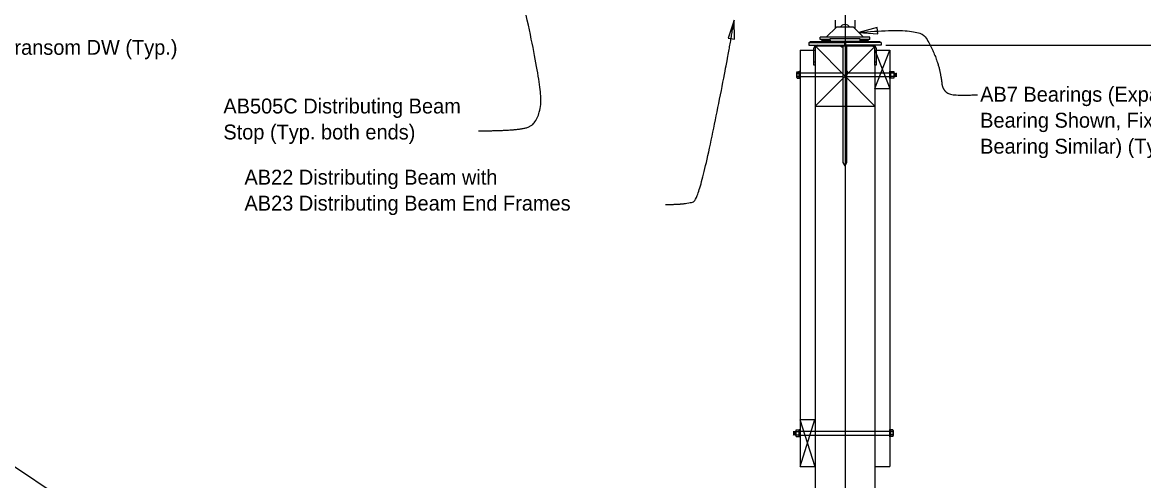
# Model space of a CAD drawing. Extents: x 3 to 58.1, y 3.3 to 34.2.
# Drawn here: x 28.56 to 47.33, y 13.88 to 21.56 of the extents above; entities that cross this region are included whole.
import ezdxf

# ---------------------------------------------------------------- set-up
doc = ezdxf.new("R2010")
doc.units = 0
for name, color, linetype in [('CL_Minor', 7, 'Continuous'), ('Dimension', 7, 'Continuous'), ('Miscellaneous', 7, 'Continuous'), ('SteelMisc', 7, 'Continuous'), ('SteelMisc_h', 7, 'Continuous'), ('TextStructures', 7, 'Continuous'), ('Wood', 7, 'Continuous')]:
    doc.layers.add(name, color=color, linetype=linetype)

msp = doc.modelspace()

# ---------------------------------------------------------------- linework, layer by layer
at = {"layer": 'CL_Minor'}
msp.add_line((42.335, 22.925), (42.335, 7.572), dxfattribs=at)
at = {"layer": 'Dimension'}
msp.add_line((43.017, 21.175), (55.391, 21.175), dxfattribs=at)
for points in [[(40.478, 21.592), (40.378, 21.292), (40.483, 21.275)], [(42.569, 21.389), (42.885, 21.365), (42.875, 21.47)]]:
    msp.add_lwpolyline(points, close=True, dxfattribs=at)
for points in [[(36.198, 19.74), (36.833, 19.74), (37.195, 19.851), (37.283, 20.5), (36.796, 22.544)], [(27.05, 21.127), (26.868, 21.142), (26.902, 21.296), (27.192, 21.546), (28.589, 21.877), (29.418, 22.176)], [(39.329, 18.506), (39.72, 18.506), (39.897, 18.616), (40.384, 20.985), (40.478, 21.592)], [(42.569, 21.389), (43.587, 21.481), (43.791, 21.128), (43.902, 20.843), (43.949, 20.607), (43.968, 20.434), (44.122, 20.318), (44.551, 20.345)]]:
    msp.add_open_spline(points, degree=2, dxfattribs=at)
at = {"layer": 'Miscellaneous'}
for p, q in [((42.855, 21.092), (42.854, 21.092)), ((19.956, 19.761), (32.606, 11.328))]:
    msp.add_line(p, q, dxfattribs=at)
at = {"layer": 'SteelMisc'}
for p, q in [((42.168, 21.592), (42.168, 21.455)), ((42.501, 21.592), (42.501, 21.454)), ((42.192, 21.477), (42.019, 21.311)), ((42.478, 21.477), (42.192, 21.477)), ((42.478, 21.477), (42.645, 21.311)), ((41.731, 21.217), (41.731, 21.175)), ((41.731, 21.217), (42.324, 21.217)), ((42.751, 21.311), (41.918, 21.311)), ((41.918, 21.269), (41.918, 21.311)), ((42.085, 21.269), (41.918, 21.269)), ((42.085, 21.259), (42.085, 21.248)), ((42.324, 21.217), (42.324, 21.175)), ((42.939, 21.217), (42.345, 21.217)), ((42.345, 21.217), (42.345, 21.175)), ((42.751, 21.269), (42.585, 21.269)), ((42.585, 21.259), (42.585, 21.248)), ((42.751, 21.269), (42.751, 21.311)), ((42.939, 21.217), (42.939, 21.175)), ((41.731, 21.175), (42.324, 21.175)), ((41.814, 20.842), (41.814, 21.123)), ((41.835, 21.123), (41.835, 20.842)), ((41.866, 21.175), (42.803, 21.175)), ((42.803, 21.155), (41.866, 21.155)), ((42.939, 21.175), (42.345, 21.175)), ((42.835, 20.842), (42.835, 21.123)), ((42.855, 21.123), (42.855, 20.842)), ((41.814, 20.898), (41.835, 20.898)), ((41.835, 20.842), (41.814, 20.842)), ((42.835, 20.898), (42.855, 20.898)), ((42.855, 20.842), (42.835, 20.842)), ((41.528, 20.634), (41.528, 20.717)), ((41.532, 20.73), (41.57, 20.73)), ((41.532, 20.703), (41.57, 20.703)), ((42.366, 20.742), (42.366, 20.741)), ((43.153, 20.73), (43.099, 20.73)), ((43.153, 20.703), (43.099, 20.703)), ((43.157, 20.634), (43.157, 20.717)), ((43.159, 20.696), (43.157, 20.699)), ((43.158, 20.644), (43.157, 20.657)), ((43.162, 20.655), (43.158, 20.644)), ((43.163, 20.707), (43.159, 20.696)), ((43.168, 20.644), (43.162, 20.655)), ((43.168, 20.644), (43.163, 20.707)), ((43.169, 20.696), (43.163, 20.707)), ((43.173, 20.655), (43.168, 20.644)), ((43.173, 20.707), (43.169, 20.696)), ((43.179, 20.644), (43.173, 20.707)), ((43.179, 20.696), (43.173, 20.707)), ((43.179, 20.644), (43.173, 20.655)), ((43.184, 20.707), (43.179, 20.696)), ((43.183, 20.655), (43.179, 20.644)), ((43.189, 20.644), (43.183, 20.655)), ((43.189, 20.644), (43.184, 20.707)), ((43.19, 20.696), (43.184, 20.707)), ((43.193, 20.655), (43.189, 20.644)), ((43.194, 20.707), (43.19, 20.696)), ((43.197, 20.648), (43.193, 20.655)), ((43.197, 20.668), (43.194, 20.707)), ((43.197, 20.701), (43.194, 20.707)), ((43.197, 20.648), (43.197, 20.701)), ((41.532, 20.648), (41.57, 20.648)), ((41.532, 20.621), (41.57, 20.621)), ((43.153, 20.648), (43.099, 20.648)), ((43.153, 20.621), (43.099, 20.621)), ((43.158, 20.644), (43.157, 20.646)), ((41.472, 14.703), (41.472, 14.65)), ((41.472, 14.703), (41.476, 14.696)), ((41.472, 14.683), (41.475, 14.644)), ((41.472, 14.65), (41.475, 14.644)), ((41.475, 14.644), (41.48, 14.655)), ((41.476, 14.696), (41.48, 14.707)), ((41.48, 14.707), (41.486, 14.644)), ((41.48, 14.707), (41.486, 14.696)), ((41.48, 14.655), (41.486, 14.644)), ((41.486, 14.696), (41.491, 14.707)), ((41.486, 14.644), (41.49, 14.655)), ((41.49, 14.655), (41.496, 14.644)), ((41.491, 14.707), (41.496, 14.644)), ((41.491, 14.707), (41.497, 14.696)), ((41.496, 14.644), (41.5, 14.655)), ((41.497, 14.696), (41.501, 14.707)), ((41.5, 14.655), (41.507, 14.644)), ((41.501, 14.707), (41.507, 14.644)), ((41.501, 14.707), (41.507, 14.696)), ((41.507, 14.696), (41.512, 14.707)), ((41.507, 14.644), (41.511, 14.655)), ((41.511, 14.655), (41.513, 14.652)), ((41.512, 14.707), (41.513, 14.694)), ((41.512, 14.707), (41.513, 14.705)), ((41.513, 14.717), (41.513, 14.634)), ((41.517, 14.73), (41.57, 14.73)), ((41.517, 14.703), (41.57, 14.703)), ((41.517, 14.648), (41.57, 14.648)), ((43.137, 14.73), (43.099, 14.73)), ((43.137, 14.703), (43.099, 14.703)), ((43.137, 14.648), (43.099, 14.648)), ((43.141, 14.717), (43.141, 14.634)), ((41.517, 14.621), (41.57, 14.621)), ((43.137, 14.621), (43.099, 14.621))]:
    msp.add_line(p, q, dxfattribs=at)
for points in [[(41.751, 21.22), (41.751, 21.238), (42.918, 21.238), (42.918, 21.217)], [(42.085, 21.248), (41.939, 21.248), (41.939, 21.238)], [(42.085, 21.259), (42.001, 21.259), (42.001, 21.269)], [(42.668, 21.269), (42.668, 21.259), (42.585, 21.259)], [(42.731, 21.238), (42.731, 21.248), (42.585, 21.248)]]:
    msp.add_lwpolyline(points, dxfattribs=at)
for points in [[(42.585, 21.238), (42.085, 21.238), (42.085, 21.288), (42.585, 21.288)], [(42.241, 21.175), (42.428, 21.175), (42.428, 21.155), (42.241, 21.155)], [(41.57, 20.737), (41.585, 20.737), (41.585, 20.614), (41.57, 20.614)], [(43.085, 20.737), (43.099, 20.737), (43.099, 20.614), (43.085, 20.614)], [(41.585, 14.614), (41.57, 14.614), (41.57, 14.737), (41.585, 14.737)], [(43.099, 14.614), (43.085, 14.614), (43.085, 14.737), (43.099, 14.737)]]:
    msp.add_lwpolyline(points, close=True, dxfattribs=at)
for centre, radius, start, end in [((42.335, 21.415), 0.104, 36.8424, 143.1576), ((41.866, 21.123), 0.052, 90, 180), ((41.866, 21.123), 0.0312, 90, 180), ((42.803, 21.123), 0.052, 0, 90), ((42.803, 21.123), 0.0312, 0, 90), ((41.553, 20.717), 0.0248, 146.5255, 213.4745), ((41.621, 20.675), 0.093, 162.8979, 197.1021), ((43.132, 20.717), 0.0248, 326.5255, 33.4745), ((43.064, 20.675), 0.093, 342.8979, 17.1021), ((41.553, 20.634), 0.0248, 146.5255, 213.4745), ((43.132, 20.634), 0.0248, 326.5255, 33.4745), ((41.537, 14.717), 0.0248, 146.5255, 213.4745), ((41.606, 14.675), 0.093, 162.8979, 197.1021), ((41.537, 14.634), 0.0248, 146.5255, 213.4745), ((43.116, 14.717), 0.0248, 326.5255, 33.4745), ((43.048, 14.675), 0.093, 342.8979, 17.1021), ((43.116, 14.634), 0.0248, 326.5255, 33.4745)]:
    msp.add_arc(centre, radius, start, end, dxfattribs=at)
at = {"layer": 'SteelMisc_h'}
for p, q in [((42.303, 19.209), (42.303, 21.155)), ((42.366, 19.209), (42.366, 21.155)), ((42.298, 20.707), (41.585, 20.707)), ((43.085, 20.707), (42.366, 20.707)), ((42.303, 20.644), (41.585, 20.644)), ((43.085, 20.644), (42.366, 20.644)), ((42.335, 19.155), (42.303, 19.209)), ((42.335, 19.155), (42.366, 19.209)), ((41.585, 14.707), (43.085, 14.707)), ((41.585, 14.644), (43.085, 14.644))]:
    msp.add_line(p, q, dxfattribs=at)
at = {"layer": 'Wood'}
for p, q in [((41.585, 21.092), (41.835, 21.092)), ((41.585, 21.092), (41.585, 14.118)), ((41.835, 20.155), (42.84, 21.155)), ((41.84, 21.155), (42.835, 20.155)), ((42.228, 21.171), (42.241, 21.165)), ((42.266, 21.155), (42.279, 21.149)), ((42.279, 21.149), (42.303, 21.139)), ((42.835, 21.092), (43.085, 21.092)), ((42.835, 21.092), (43.085, 20.446)), ((42.835, 20.446), (43.085, 21.092)), ((43.085, 21.092), (43.085, 14.118)), ((41.835, 20.842), (41.835, 11.278)), ((42.835, 20.842), (42.835, 11.299)), ((42.366, 20.741), (42.386, 20.707)), ((42.366, 20.677), (42.383, 20.707)), ((42.835, 20.446), (43.085, 20.446)), ((41.835, 20.155), (42.835, 20.155)), ((41.581, 14.905), (41.831, 14.118)), ((41.583, 14.905), (41.831, 14.905)), ((41.585, 14.118), (41.831, 14.905)), ((41.585, 14.118), (41.831, 14.118)), ((42.835, 14.118), (43.085, 14.118))]:
    msp.add_line(p, q, dxfattribs=at)

# ---------------------------------------------------------------- texts
at = {"layer": 'Dimension'}
for s, p in [('AB505C Distributing Beam', (31.925, 20.03)), ('Stop (Typ. both ends)', (31.925, 19.595))]:
    msp.add_text(s, height=0.25, dxfattribs=at).set_placement(p)
at = {"layer": 'TextStructures'}
for s, p in [('AB306 Transom DW (Typ.)', (27.126, 21.013)), ('AB7 Bearings (Expansion ', (44.598, 20.227)), ('Bearing Shown, Fixed ', (44.598, 19.792)), ('Bearing Similar) (Typ.)', (44.598, 19.357)), ('AB22 Distributing Beam with ', (32.278, 18.838)), ('AB23 Distributing Beam End Frames', (32.278, 18.403))]:
    msp.add_text(s, height=0.25, dxfattribs=at).set_placement(p)

doc.saveas('drawing.dxf')
